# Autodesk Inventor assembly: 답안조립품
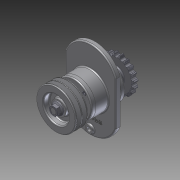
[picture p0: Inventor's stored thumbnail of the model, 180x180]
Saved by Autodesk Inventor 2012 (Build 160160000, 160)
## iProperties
Created: 2015-02
Part Number: 답안조립품
Document SubType Name: Assembly
Designer: Class3-User
Author: Class3-User
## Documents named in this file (12)
- C:\Users\Class3-User\Desktop\450208V1014\답안조립품.iam
- C:\Users\Class3-User\Desktop\450208V1014\2-커버.ipt
- C:\Users\Class3-User\Desktop\450208V1014\1 본체.ipt
- C:\Users\Class3-User\Desktop\450208V1014\3-축.ipt
- C:\Users\Class3-User\Desktop\450208V1014\4-V벨트풀리.ipt
- C:\Users\Class3-User\Desktop\450208V1014\5-체인 스프로킷.ipt
- C:\Users\Class3-User\Desktop\450208V1014\6-베어링 6206.ipt
- C:\Users\Class3-User\Desktop\450208V1014\7-부시.ipt
- C:\Users\Class3-User\Desktop\450208V1014\11-키 6x6.ipt
- C:\Users\Class3-User\Desktop\450208V1014\8-오일실 30x42.ipt
- C:\Users\Class3-User\Desktop\450208V1014\9-M16-너트.ipt
- C:\Users\Class3-User\Desktop\450208V1014\10-M6.ipt
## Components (23 placed, 11 different names)
1. 1 본체:1 — 플러쉬:1
2. 2-커버:1
3. 2-커버:2
4. 3-축:1
5. 4-V벨트풀리:1
6. 5-체인 스프로킷:1
7. 6-베어링 6206:1
8. 6-베어링 6206:2
9. 7-부시:1
10. 11-키 6x6:1
11. 11-키 6x6:2
12. 8-8-오일실 30x42:1
13. 8-8-오일실 30x42:2
14. 9-M16 너트:1
15. 9-M16 너트:2
16. 10-M6:1
17. 10-M6:2
18. 10-M6:3
19. 10-M6:4
20. 10-M6:5
21. 10-M6:6
22. 10-M6:7
23. 10-M6:8
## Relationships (1: Flush 1)
- 플러쉬:1 [Flush]: 1 본체:1
